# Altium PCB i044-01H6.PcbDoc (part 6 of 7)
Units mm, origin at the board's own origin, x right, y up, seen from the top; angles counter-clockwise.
Board outline 42 x 29.01 mm, 8 copper layers (Top Layer, Mid-Layer 1, Mid-Layer 2, Mid-Layer 3, Mid-Layer 4, Mid-Layer 5, Mid-Layer 6, Bottom Layer), stack 1.474 mm thick; 235 components, 197 nets, 1006 pads, 1183 vias.
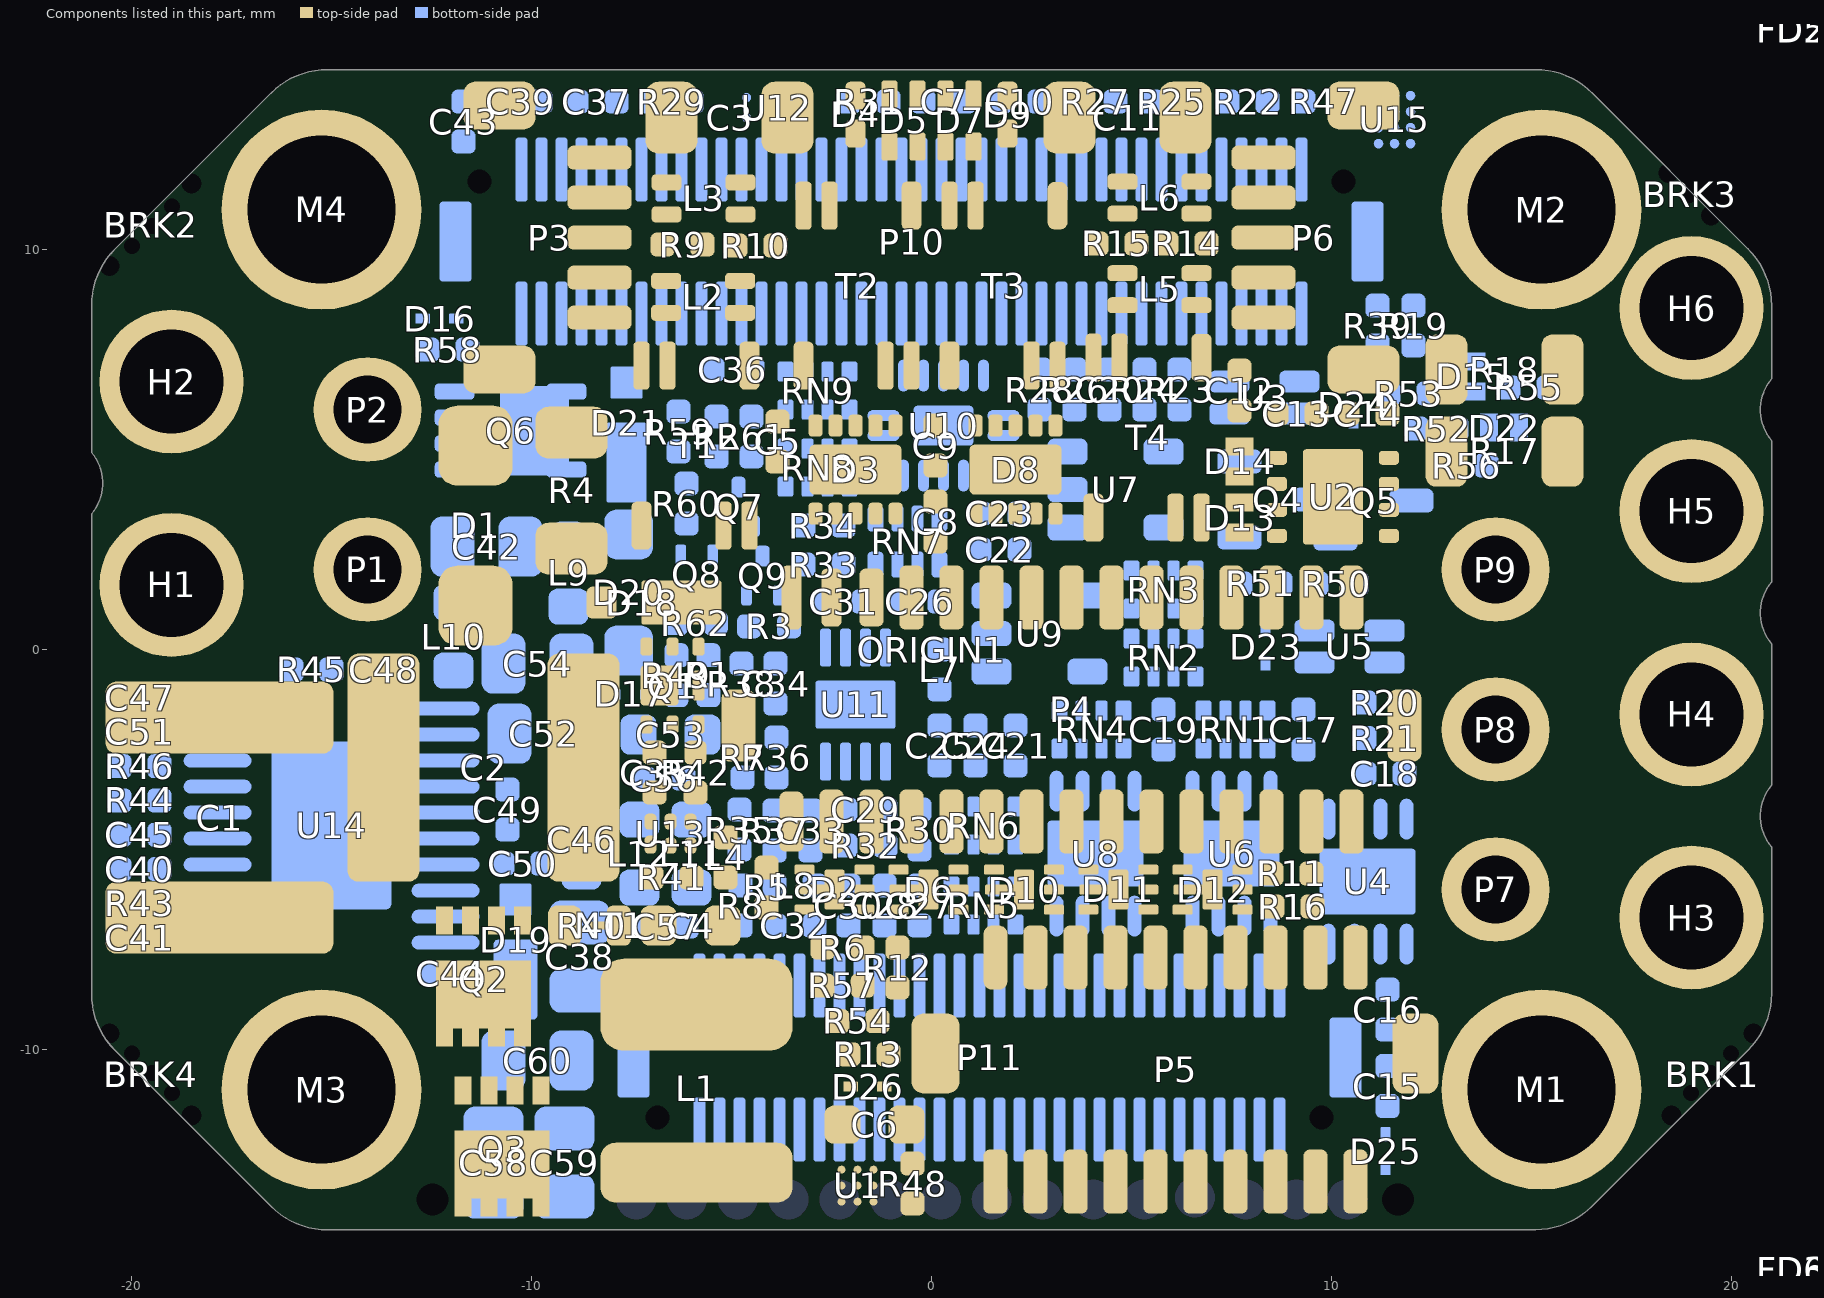
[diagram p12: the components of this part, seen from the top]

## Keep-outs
Top Layer:
  lines w0.2: 9,0.075 9,2.375 ; 10,0.035 10,2.5
  lines w0.25: 12.097,5.975 17.059,5.975
  lines w0.3: -8.075,-6.175 -4.865,-6.166 -4.601,-6.429 -4.6,-6.726 -4.048,-7.276 -3.902,-7.275 -3.227,-7.947 -3.222,-9.945 -3.777,-10.502 -3.774,-11.465 -3.535,-11.704 -3.535,-11.93 -3.259,-12.206 -3.259,-14.425 ; -3.379,-10.15 -3.373,-12.092
  lines w0.4: -9.601,0.125 -8.875,0.125 ; -8.748,0.148 -7.844,0.148 -7.55,-0.147 -7.55,-0.382
  lines w0.49: -7.875,-6.075 -7.55,-5.75 -7.55,-0.382
  lines w0.5: -19,10.3 -18.69,10.3 -16.82,8.43 -16.33,7.94 -13.12,7.94 -9.587,7.94 -9.38,7.733 ; -17.84,-12.064 cw(c-15.25,-11) -16.754,-13.362 ; -14.6,-8.3 -14.6,-6.55 -14.125,-6.075 -11.275,-6.075 ; -10.19,0.038 -10.19,0.914 -10.19,1.79 -10.19,6.01 -10.026,6.174 ; -10.025,-1.175 -10.025,-0.299 -9.951,-0.225 -9.601,0.125 ; -10.021,-0.778 -10.021,-4.821 -11.275,-6.075 ; -9.841,6.273 -9.538,6.575 -9.222,6.575 -8.722,7.075 ; -9.38,10.71 -9.38,7.733 ; -7.875,-6.075 -11.275,-6.075 ; -7.76,3.475 -7.76,3.957 -7.567,4.151 -7.567,5.92 -9.38,7.733 ; -7.76,3.7 -7.76,3.57 -7.76,2.47 -7.73,2.44 -7.53,2.24 -7.39,2.24 -6.86,2.24 -6.77,2.33 -6.32,2.78 -6.32,3.36 -6.32,4.13 -5.07,5.38 -5.07,7.8 -4.91,7.96 -4.77,7.96 -4.16,7.96 -4.05,7.85 -3.92,7.72 -3.92,7.28 -3.92,6.65 -3.71,6.44 -3.42,6.15 -3.32,6.15 -2.91,6.15 -2.8,6.26 -1.92,7.14 -1.92,9.81 -1.92,11.84 -2.31,12.23 -2.5,12.42 -2.5,14.48 ; -7.38,11.82 -7.06,12.14 -6.68,12.14 -5.94,12.14 ; -5.575,14.674 -5.575,13.202 -5.575,12.505 -5.94,12.14 ; 2.425,14.5 2.425,12.61 2.65,12.385 3.06,11.975 3.575,11.975 3.675,11.875 3.675,11.65 ; 3.246,10.247 ccw(c3.259,10.627) 3.618,10.503 ; 3.269,10.225 2.675,10.225 1.575,11.325 1.575,11.8 1.404,11.971 0.221,11.971 -0.004,11.746 -0.004,8.721 -0.05,8.675 -0.05,6.45 0.2,6.2 0.825,6.2 1.475,6.85 1.475,7.3 2.25,8.075 3.475,8.075 3.604,7.946 3.604,4.435 3.548,4.38 3.548,2.617 3.765,2.4 4.725,2.4 5.3,2.975 5.3,3.915 6.125,4.74 6.125,7.875 6.4,8.15 6.965,8.15 7.1,8.15 7.225,8.025 7.275,7.975 7.275,7.675 7.375,7.575 7.65,7.575 ; 3.665,10.565 3.665,11.715 ; 12.175,1.825 12.175,1.3 10.95,0.075 ; -5.94,12.14 -5.94,12.14 ; 8.175,2.375 7.15,2.375 7.05,2.275 7.05,0.25 7.225,0.075 8.225,0.075 ; 8.175,2.375 8,2.2 8,0.3 8.225,0.075 ; 8.175,2.375 9.873,2.375 10.793,2.375 11.079,2.089 11.079,0.204 10.95,0.075 ; 8.225,0.075 10.95,0.075
  lines w0.6: 7.55,7.6 9.125,7.6 9.65,7.6 10,7.95 11.85,7.95 12.1,8.2 13.75,8.2 15.325,8.2 16.435,8.2 17.05,7.585 17.05,4.538 16.396,3.884 16.075,3.725 12.375,3.725 ; 11.95,8.05 12.025,7.975 12.025,6.771 12.025,4.1 12.35,3.775 12.35,2.3 12.35,2 12.175,1.825
Mid-Layer 1:
  circle w0.5: c15.25,-11 r2.26
  circle w0.5: c-15.25,-11 r2.26
  circle w0.4: c-15.25,11 r2.3
  lines w0.2: 0.825,11.6 2.65,11.6 2.875,11.825 2.875,13.225 2.643,13.408 2.591,13.85 2.636,13.895 5.415,13.895 5.605,13.705 5.605,12.68 5.605,12.37
  lines w0.3: -7.525,-4.95 -7.523,-5.744 -7.093,-6.172 -4.865,-6.166 -4.601,-6.429 ; -4.048,-7.276 -4.6,-6.726 ; -4.002,-7.268 -3.993,-10.467 -3.709,-10.75 ; -3.223,-9.425 -3.223,-9.399 ; -4.601,-6.429 -4.6,-6.726 ; -4.601,-6.429 -4.6,-6.726
  lines w0.4: -11.35,-7.6 -9.887,-7.6 -9.887,-9.161 -7.788,-11.26 -7.26,-11.26 -7.062,-11.062 ; -11.35,-7.598 -13.243,-7.598 -13.725,-8.08 -13.725,-9.181 -12.975,-9.931 -12.975,-12.6 -13.25,-12.875 -13.25,-14.234 -12.984,-14.5 -7.775,-14.5 -7.775,-13.6 -5.993,-11.818 -5.993,-11.875 ; -7.8,-14.5 -3.575,-14.5 -3.425,-14.35 -3.425,-11.675 -3.625,-11.875 -5.993,-11.875 ; -7.062,-11.062 -6.43,-11.062 ; -7.062,-11.062 -6.43,-11.062 ; -6.43,-11.062 -6.267,-11.225 -6.267,-11.601 -5.993,-11.875
  lines w0.5: -14.2,14.499 -12.403,12.702 -12.403,9.103 -10.991,7.691 ; -11.25,7.975 -10.346,7.03 -10.068,6.753 -10.068,2.408 -8.96,1.3 -7.575,-0.085 -7.575,-5.023 ; -3.709,-10.75 -3.49,-10.969 -3.49,-11.175 -3.49,-11.675 ; -3.15,-14.275 -3.15,-13.591 ; 1.571,11.746 -0.004,11.746 -0.004,8.721 -0.004,6.404 0.2,6.2 1.475,6.2 1.475,6.595 1.921,7.041 1.921,7.621 2.246,7.946 ; 2.82,13.725 5.4,13.725 5.4,12.449 5.709,12.14 6.908,12.14 7.658,12.89 9.16,12.89 9.575,12.475 9.575,9.025 8.15,7.6 6.75,7.6 6.125,6.975 6.125,4.4 5.64,3.915 5.129,3.404 3.885,3.404 3.604,3.685 3.604,8.04 ; 15.25,8.74 cw(c15.25,11) 16.962,12.475 ; -9.38,7.68 -7.575,5.875 -7.575,3.755 -7.575,3.385 -7.575,2.655 -7.345,2.425 -6.675,2.425 -6.32,2.78 -6.32,3.36 -6.32,4.765 -5.705,5.38 -5.07,5.38 -4.01,6.44 -3.71,6.44 -3.4,6.75 -2.31,6.75 -1.92,7.14 -1.92,9.81 -1.92,11.84 -2.31,12.23 -2.31,12.711 -2.31,13.447 -2.61,13.747 -2.61,14.48 -2.615,14.475 -5.575,14.475 -5.575,13.202 -5.575,12.505 -5.94,12.14 -6.68,12.14 -7.06,12.14 -8.56,12.14 -9.38,11.32 -9.38,7.68
Mid-Layer 2:
  circle w0.5: c15.25,-11 r2.26
  circle w0.5: c-15.25,-11 r2.26
  circle w0.4: c-15.25,11 r2.3
  lines w0.2: 2.6,12.325 2.9,12.625 2.9,12.975 2.65,13.95
  lines w0.3: -4.6,-6.726 -4.048,-7.276 -3.227,-8.093 -3.223,-9.425
  lines w0.4: -13.167,-14.475 -13.167,-11.898 ; -7.8,-14.5 -3.575,-14.5 -3.425,-14.35 ; -7.462,-12.688 -7.775,-13 -7.775,-14.5 ; -13.167,-14.5 -13.167,-11.898 ; -13.167,-14.5 -7.775,-14.5 ; -13.167,-14.5 -7.775,-14.5 ; -13.167,-11.898 -12.918,-11.65 -13.167,-11.898
  lines w0.48: -8.403,1.265 -8.051,0.913 ; -7.575,-4.536 -6.884,-5.227 -6.318,-5.227 -5.663,-5.882 -5.438,-5.882 -4.603,-6.716 ; -7.462,-12.688 -7.462,-11.488 -6.8,-10.825
  lines w0.5: -20.7,4.2 -12.475,4.2 ; -14.2,14.499 -12.475,12.774 -12.475,5.95 -12.475,0.863 ; -12.92,0.418 -11.531,0.463 ; -12.875,0.463 -11.531,0.463 ; -12.418,8.207 -10.175,5.965 -10.175,2.129 -9.671,1.625 ; -12.413,0.925 -13.213,0.125 ; -9.15,1.5 -8.638,1.5 ; -7.575,-4.536 -7.575,-0.04 -7.575,0.437 -8.403,1.265 -8.638,1.5 ; -6.8,-10.825 -4.603,-8.628 -4.603,-6.716 ; -3.15,-14.275 -3.15,-9.114 ; 15.25,8.74 cw(c15.25,11) 16.962,12.475 ; -17.8,-0.6 -21,-0.6 -17.8,-0.6 ; -17.8,-0.6 -16.047,0.1 ; -17.8,-0.6 -16.047,0.1 ; -16.047,0.1 -13.213,0.125 ; -16.047,0.1 -13.213,0.125 ; -16.047,0.1 -13.213,0.125 ; -13.213,0.125 -12.475,0.863 ; -13.213,0.125 -12.475,0.863 ; -11.531,0.463 -10.994,1 -10.494,1.5 -8.637,1.5 ; -9.38,7.68 -7.575,5.875 -7.575,3.755 -7.575,3.385 -7.575,2.655 -7.345,2.425 -6.675,2.425 -6.32,2.78 -6.32,3.36 -6.32,4.755 -5.695,5.38 -5.07,5.38 -4.01,6.44 -3.71,6.44 -2.62,6.44 -1.92,7.14 -1.92,9.81 -1.92,11.84 -2.31,12.23 -2.61,12.53 -2.61,14.48 -2.615,14.475 -5.575,14.475 -5.575,13.202 -5.575,12.505 -5.94,12.14 -6.68,12.14 -7.06,12.14 -7.325,11.875 -8.825,11.875 -9.38,11.32 -9.38,7.68 ; -0.004,6.404 0.2,6.2 0.825,6.2 1.475,6.85 1.475,7.175 2.246,7.946 3.429,7.946 3.604,7.771 3.604,3.685 4,3.288 5.013,3.288 5.64,3.915 6.125,4.4 6.125,6.975 6.75,7.6 8.15,7.6 9.575,9.025 9.575,14.325 2.6,14.325 2.6,12.325 2.6,12.061 2.314,11.775 1.6,11.775 1.404,11.971 0.221,11.971 -0.004,11.746 -0.004,8.721 -0.004,6.404
Mid-Layer 3:
  circle w0.5: c15.25,-11 r2.26
  circle w0.5: c-15.25,-11 r2.26
  circle w0.4: c-15.25,11 r2.3
  rectangle: -7.85,-4.525 -5.25,-3.8
  lines w0.4: -13.167,-14.5 -3.335,-14.5 ; -13.167,-14.475 -13.167,-11.898
  lines w0.48: -8.5,0.922 -8.051,0.473 -8.051,-4.015 -6.839,-5.227 -5.473,-5.227 -4.7,-6 -4.7,-8.26 ; -7.526,-4.54 -6.19,-5.875 -4.85,-5.875 ; -7.278,-4.602 -5.475,-4.602 ; -6.975,-4.977 -5.45,-4.977 ; -6.221,-5.575 -5.614,-5.575 -4.766,-6.423 ; -5.5,-5.875 -5.5,-4.072
  lines w0.5: -20.7,4.2 -12.475,4.2 ; -14.2,14.499 -12.475,12.774 -12.475,5.95 -12.475,0.863 ; -12.875,0.463 -11.531,0.463 -10.994,1 -10.494,1.5 -9.078,1.5 ; -12.426,0.912 -13.213,0.125 ; -10.175,5.15 -10.175,5.965 ; -8.5,0.922 -9.078,1.5 ; -4.65,-8.26 -3.15,-9.76 -3.15,-14.275 ; 15.25,8.74 cw(c15.25,11) 16.962,12.475 ; -17.8,-0.6 -21,-0.6 -17.8,-0.6 ; -17.8,-0.6 -16.047,0.1 ; -17.8,-0.6 -16.047,0.1 ; -16.047,0.1 -13.213,0.125 ; -16.047,0.1 -13.213,0.125 ; -16.047,0.1 -13.213,0.125 ; -13.213,0.125 -12.475,0.863 ; -13.213,0.125 -12.475,0.863 ; -10.175,5.965 -12.418,8.207 -10.175,5.965 ; -10.175,5.965 -10.175,2.129 -9.546,1.5 -9.078,1.5
Mid-Layer 4:
  circle w0.5: c15.25,-11 r2.26
  circle w0.5: c-15.25,-11 r2.26
  circle w0.4: c-15.25,11 r2.3
  lines w0.4: -13.167,-14.5 -7.775,-14.5 ; -13.167,-14.475 -13.167,-11.995 ; -7.775,-14.5 -7.775,-12.525 -7.775,-14.5
  lines w0.48: -9.484,0.718 -8.579,0.718 ; -7.9,-4.977 -5.723,-4.977 -5.2,-5.5 ; -7.775,-12.525 -7.05,-12.525 -6.275,-11.75 -6.275,-11.05 -4.85,-9.625 -4.85,-5.85 -5.473,-5.227 -7.65,-5.227 -8.051,-4.826 -8.051,0.19 ; -8.579,0.718 -8.051,0.19 ; -8.579,0.718 -8.051,0.19
  lines w0.5: -20.7,4.2 -12.475,4.2 ; -14.2,14.499 -12.475,12.774 -12.475,5.95 -12.475,0.863 ; -12.875,0.463 -11.531,0.463 ; -12.425,2.775 -11.443,1.793 ; -12.375,1.793 -10.201,1.793 -8.87,1.793 -8.579,1.502 -8.579,0.718 ; -8.125,0.225 -8.7,0.8 -10.968,0.8 -11.349,0.418 -12.92,0.418 -13.213,0.125 ; 15.25,8.74 cw(c15.25,11) 16.962,12.475 ; -17.8,-0.6 -21,-0.6 -17.8,-0.6 ; -17.8,-0.6 -16.047,0.1 ; -17.8,-0.6 -16.047,0.1 ; -16.047,0.1 -13.213,0.125 ; -16.047,0.1 -13.213,0.125 ; -16.047,0.1 -13.213,0.125 ; -13.213,0.125 -12.475,0.863 ; -13.213,0.125 -12.475,0.863
Mid-Layer 5:
  circle w0.4: c-15.25,11 r2.3
  circle w0.5: c15.25,-11 r2.26
  circle w0.5: c-15.25,-11 r2.26
  rectangle: -8.1,-5.15 -5.25,-3.8
  lines w0.3: -5.3,-5.4 -5.3,-4.977
  lines w0.4: -13.167,-12.008 -13.167,-14.5 -7.775,-14.5 ; -7.775,-13 -7.775,-14.5 ; -7.575,-12.4 -7.775,-12.6 -7.775,-14.5
  lines w0.48: -9.484,1.793 -8.579,1.793 -8.051,1.265 -8.051,-4.826 -7.65,-5.227 -5.473,-5.227 -4.875,-5.825 -4.875,-9.635 -6.275,-11.035 -6.275,-12.4 -7.575,-12.4 ; -7.9,-4.977 -5.4,-4.977 ; -6.282,-10.882 -6.273,-8.979 -5.672,-8.383 -5.099,-8.386
  lines w0.5: -20.7,4.2 -12.475,4.2 ; -14.2,14.499 -12.475,12.774 -12.475,5.95 -12.475,0.863 ; -12.875,0.463 -11.531,0.463 ; -12.425,2.775 -11.443,1.793 -11.288,1.793 ; -12.375,1.793 -10.201,1.793 -8.775,1.793 ; -8.051,0.8 -10.968,0.8 -11.349,0.418 -12.92,0.418 -13.213,0.125 ; 15.25,8.74 cw(c15.25,11) 16.962,12.475 ; -17.8,-0.6 -21,-0.6 -17.8,-0.6 ; -17.8,-0.6 -16.047,0.1 ; -17.8,-0.6 -16.047,0.1 ; -16.047,0.1 -13.213,0.125 ; -16.047,0.1 -13.213,0.125 ; -16.047,0.1 -13.213,0.125 ; -13.213,0.125 -12.475,0.863 ; -13.213,0.125 -12.475,0.863
Mid-Layer 6:
  circle w0.4: c-15.25,11 r2.3
  circle w0.5: c15.25,-11 r2.26
  circle w0.5: c-15.25,-11 r2.26
  circle w0.3: c10.975,3.2 r0.469
  circle w0.3: c10,3.225 r0.469
  circle w0.3: c8.25,3.775 r0.469
  rectangle: -8.1,-5.15 -5.25,-3.8
  lines w0.3: -10.575,7.25 -10.45,7.125 -8.282,7.125 ; -5.3,-5.4 -5.3,-4.75 -5.3,-3.95 ; 10.111,4.5 10.638,4.5 10.925,4.787 10.925,5.2 ; 10.92,5.211 10.92,5.445 11.55,6.075 11.55,6.35
  lines w0.4: -13.167,-12.031 -13.167,-14.5 -7.775,-14.5 -7.775,-13 -7.65,-12.875 ; -8.975,-14.525 -8.854,-14.525 ; -5.934,-8.398 -5.55,-8.013
  lines w0.48: -8.825,1.986 -8.051,1.212 -8.051,0.8 -8.051,-4.826 -7.65,-5.227 -5.473,-5.227 -5.1,-5.6 -5.1,-7.425 -5.55,-7.875 -5.55,-8.013 ; -7.9,-4.977 -5.4,-4.977 ; -7.65,-12.875 -6.75,-12.875 -6.275,-12.4 ; -6.285,-11.475 -6.271,-8.596 -6.073,-8.398 -5.934,-8.398 ; -6.275,-9.425 -5.65,-10.05 -5.65,-10.475 -6.271,-11.096 -6.271,-12.4
  lines w0.5: -21,-0.6 -17.8,-0.6 -16.047,0.1 ; -20.7,4.2 -12.475,4.2 ; -14.2,14.499 -12.069,12.368 -12.069,8.675 -12.842,8.675 ; -12.875,0.463 -11.531,0.463 ; -12.525,8.675 -12,8.675 -10.575,7.25 ; -12.475,6.79 -12.475,0.863 -13.213,0.125 ; -8.825,1.986 -8.825,3.947 -8.81,3.962 -8.81,4.789 -8.81,5.765 ; -8.825,2.453 -10.478,0.8 -10.968,0.8 ; -8.051,0.8 -10.968,0.8 ; 6.95,2.4 6.875,2.475 6.875,3.925 6.875,4.86 7.24,5.225 9.386,5.225 10.111,4.5 ; 7.075,2.275 7.075,1.595 7.91,0.76 7.91,-0.129 8.307,-0.525 10.3,-0.525 10.3,-0.173 10.425,-0.048 10.425,0.685 10.79,1.05 11.968,1.05 12.4,1.482 12.4,3.371 13.179,4.15 16.3,4.15 16.625,4.475 16.625,7.04 15.94,7.725 14.075,7.725 13.53,7.18 12.38,7.18 12.075,6.875 11.55,6.35 ; 15.25,8.74 cw(c15.25,11) 16.962,12.475 ; -16.047,0.1 -13.213,0.125 ; -16.047,0.1 -13.213,0.125 ; -13.213,0.125 -12.92,0.418 -11.349,0.418 ; -11.349,0.418 -10.968,0.8 ; -11.349,0.418 -10.968,0.8
Bottom Layer:
  lines w0.19: -5.98,-1.45 -5.98,-0.87
  lines w0.198: -5.11,3.93 -5.11,4.38 ; -4.85,3.69 cw(c-4.84,3.69) -4.84,3.7 -4.625,3.7 -4.025,4.3 ; -2.5,7.481 -2.046,7.481 -2,7.527 -2,9.2 -2.1,9.3 -2.4,9.3 -2.5,9.2 -2.5,7.481 ; -2.5,11.2 -2.5,12.8 -2.376,12.924 -2,12.924 -2,11.2 -2.1,11.1 -2.4,11.1 -2.5,11.2
  lines w0.2: -11.086,1.525 -9.925,1.525 -9.715,1.735 -8.603,1.735 -8.35,1.482 -8.35,-1.25 -8.051,-1.549 ; -8.051,-1.625 -8.051,-1.549 ; -7.61,-1.46 -6.965,-1.46 -6.875,-1.55 -6.08,-1.55 -5.98,-1.45 ; -6.875,5.425 -5.943,5.425 -5.843,5.325 -5.2,5.325 -4.925,5.6 -4.925,6.275 ; -6.8,-0.57 -6.28,-0.57 -5.98,-0.87 ; -5.9,6.4 -6.725,6.4 -6.9,6.225 -6.9,5.43 -6.74,5.27 -6.74,3.961 -6.53,3.751 -6.53,1.52 -6.8,1.25 -6.8,-0.562 -7.011,-0.774 -7.334,-0.774 -7.49,-0.93 -7.49,-1.325 -7.714,-1.549 -8.051,-1.549 ; -5.868,6.4 -5.868,4.618 -5.625,4.375 -5.1,4.375 ; -5.3,-4.75 -5.3,-3.95 -5.55,-3.7 -5.55,-2.975 -5.145,-2.57 -5.145,-1.712 -5.175,-1.682 -5.175,-0.075 -5.029,0.071 -3.32,0.071 -3.125,0.266 -3.125,1.35 -3.625,1.85 -3.625,3.3 -3.975,3.65 ; -5.125,4.35 cw(c-5.1,4.35) -5.1,4.375 ; -5.115,3.945 ccw(c-4.86,3.945) -4.86,3.69 ; -4.05,5.3 -4.7,5.3 -4.95,5.05 -4.95,4.525 -5.1,4.375 ; -3.975,3.725 -3.975,3.65 ; -3.975,4.45 -3.975,3.65 ; 7.075,5.3 6.8,5.575 4.219,5.575 4.025,5.769 4.025,6.297 4.185,6.457 6.593,6.457 6.76,6.29 8,6.29 ; 8.211,5.3 8.375,5.136 8.375,3.525 9.175,2.725 9.175,2.65 9.475,2.35 10.65,2.35 11.275,1.725 ; 10.2,0.651 10.2,0.968 9.932,1.235 8.25,1.235 8.025,1.01 8.025,0.25 8.2,0.075 10.45,0.075 10.425,0.1 ; 10.425,-0.675 10.85,-0.675 11.2,-1.025 11.425,-1.025 ; 10.461,0.086 10.925,0.086 11.789,0.086 11.839,0.086 11.95,-0.025 11.95,-0.625 11.7,-0.875 11.575,-0.875 11.425,-1.025 ; 11.275,4.24 9.165,4.24 8.925,4 8.925,3.502 9.102,3.325 11.05,3.325 11.325,3.6 11.325,4.19 ; 12.275,-3.538 11.45,-3.538 11.35,-3.438 11.35,-1.1 11.425,-1.025 ; 12.893,7.15 12.893,6.282 13.166,6.009 13.634,6.009 13.725,6.1 16.306,6.1 16.825,6.619 16.825,7.05
  lines w0.3: -5.3,-7.323 -5.3,-5.425 ; -5.3,-5.4 -5.3,-4.75
  lines w0.32: -4.025,4.3 -4.025,5.975 -4.025,6.475
  lines w0.4: -10.477,7.3 -9.075,7.325 -6.25,7.325
  lines w0.48: -8.175,-14.475 -8.175,-13.4 -7.65,-12.875 -6.75,-12.875 -6.275,-12.4 -6.275,-7.505 -6.095,-7.325 -5.475,-7.325 ; -8.051,-1.625 -8.051,-4.826 -7.65,-5.227 -5.473,-5.227 ; -7.9,-4.977 -5.4,-4.977
  lines w0.5: -20.937,-0.563 -17.85,-0.563 ; -20.925,8.8 -17.575,8.8 -17.05,8.275 -16.575,7.8 -14.458,7.8 ; -17.875,-0.549 -16.072,0.114 ; -16.047,0.1 -13.213,0.125 -12.92,0.418 -11.482,0.418 -11.086,0.814 -11.086,1.525 ; -12.864,8.944 -11.676,8.944 -11.343,8.61 -10.675,7.942 -10.675,7.498 -10.477,7.3 ; -6.5,7.25 -6.2,7.25 -6.05,7.1 -6.05,6.582 -5.868,6.4 -5.9,6.4 -4.2,6.4 ; 11.275,1.1 11.275,1.725 13.5,3.95 13.875,3.95 13.9,3.925 14.575,3.925 16.025,3.925 17.425,5.325 17.637,5.537 18.739,5.737 20.821,5.737 ; 12.1,-14.499 12.1,-9.1 12.446,-8.754 ; 12.446,-1.204 12.625,-1.025 12.625,0.488 12.063,1.05 10.575,1.05 10.425,0.9 10.425,-0.675 10.225,-0.875 8.975,-0.875 7.775,-0.875 ; 13.325,7.75 16.042,7.75 ; 13.575,7.75 13.1,7.75 12.35,7 10.85,7 9.975,7 9.675,7.3 8.75,7.3 8.4,6.95 8.211,6.761 8.211,5.3 7.075,5.3 6.875,5.1 6.875,3.925 6.875,2.475 6.95,2.4 6.97,2.38 7,2.35 7.075,2.275 7.075,1.075 7.475,0.675 7.475,-0.575 7.775,-0.875 ; 14.895,7.75 16.042,7.75 ; 18.4,5.7 18.4,6.297 17.9,6.797 17.003,6.797 16.1,7.7 16.092,7.7 16.042,7.75 ; 7.775,-0.875 7.775,-0.875
  lines w0.6: -17.04,8.408 ccw(c-15.25,11) -12.864,8.944 ; -15.118,14.197 cw(c-15.25,11) -12.124,11.683 -11.046,11.683 -11.046,8.65 ; 12.446,-8.754 12.446,-1.204 ; 14.33,-14.065 cw(c15.25,-11) 18.202,-9.766 ; 15.118,7.803 cw(c15.25,11) 17.827,12.897
  lines w0.8: -18.449,-10.926 cw(c-15.25,-11) -15.631,-14.177
Keep-Out Layer:
  circle w0.15: c-12.475,-13.745 r0.45
  circle w0.2: c11.665,-13.745 r0.51
  lines w0.25: 11.7,-13.2 12.825,-13.2
  lines w0.5: -21,-0.475 -21,-8.8 -20.923,-9.186 -20.772,-9.55 -20.554,-9.878 -20.414,-10.017 -16.514,-13.916 -16.375,-14.055 -16.047,-14.274 -15.683,-14.425 -15.297,-14.502 -15.1,-14.502 15.1,-14.498 15.297,-14.498 15.683,-14.422 16.047,-14.271 16.375,-14.052 16.514,-13.913 20.414,-10.014 20.554,-9.875 20.772,-9.547 20.923,-9.183 21,-8.797 ; -21,8.797 -20.923,9.183 -20.772,9.547 -20.554,9.875 -20.414,10.014 -16.514,13.913 -16.375,14.052 -16.047,14.271 -15.683,14.422 -15.297,14.498 -15.1,14.498 15.1,14.502 15.297,14.502 15.683,14.425 16.047,14.274 16.375,14.055 16.514,13.916 18.003,12.428 ; -20.782,3.697 -20.7,4.002 -20.7,4.318 -20.782,4.623 ; 12.45,-4 12.6,-4.15 16.037,-4.15 20.7,-4.15 ; 12.5,0 15.8,0 16.7,0.9 20.7,0.9 ; 13.8,-8.275 13.25,-8.275 12.875,-7.9 12.475,-7.5 12.475,-0.8 12.475,0 12.475,3.5 13.1,4.125 14.6,4.125 16.3,4.125 16.475,4.3 16.725,4.55 16.725,4.8 18,6.075 18.35,6.075 ; 16.625,7.85 17.7,6.775 17.7,6.625 18.325,6 20.675,6 ; 20.7,5.842 20.782,5.537 ; 20.782,-3.697 20.7,-4.002 20.7,-4.318 20.786,-4.638 ; 20.782,0.457 20.7,0.762 20.7,1.078 20.782,1.383

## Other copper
Top Layer:
  rectangle net +5V_OUT: 6.9,-2.875 8.025,-0.95
  rectangle net GND_D: -1.05,13.525 1.125,14.225
  rectangle net MAGNETICS_CT: 0.1,5.325 1.175,5.875
  rectangle net GND_D: -4.2,3.875 3.2,5.1
  region net 5V_D: -2.75,-12.425 -2.656,-12.519 cw(c-2.912,-12.775) -2.55,-12.775 -2.55,-13.975 cw(c-2.7,-13.975) -2.7,-14.125 -2.975,-14.125 cw(c-2.975,-14) -3.1,-14 -3.1,-12.075
  region net +5V_OUT: -1.36,-10.725 -1.4,-10.765 -1.4,-11.061 cw(c-1.639,-11.061) -1.47,-11.23 -1.513,-11.273 ccw(c-1.379,-11.416) -1.575,-11.41 -1.575,-11.855 ccw(c-0.38,-11.855) -1.225,-12.7 -1.05,-12.7 cw(c-0.7,-12.7) -0.7,-12.35 -0.65,-12.35 0.097,-12.35 cw(c0.097,-12.672) 0.325,-12.444 cw(c0.144,-12.625) 0.4,-12.626 0.4,-13.8 ccw(c0.675,-13.8) 0.675,-14.075 1.725,-14.075 ccw(c1.725,-13.9) 1.9,-13.9 1.9,-12.626 ccw(c1.677,-12.626) 1.835,-12.468 ccw(c1.015,-13.288) 1.015,-12.129 0.897,-12.129 cw(c0.897,-11.144) 0.2,-11.84 -0.175,-11.465 ccw(c-0.356,-11.646) -0.331,-11.391 -0.409,-11.391 cw(c-0.409,-11) -0.8,-11 -0.8,-10.923 ccw(c-0.998,-10.923) -0.998,-10.725 -1.35,-10.725 ccw(c-1.35,-10.954)
  region net GND_D: -1.85,-10.725 cw(c-1.85,-10.775) -1.8,-10.775 -1.8,-11.182 ccw(c-1.732,-11.182) -1.78,-11.23 -1.771,-11.239 cw(c-1.822,-11.29) -1.75,-11.29 -1.75,-12.7 -1.85,-12.8 -1.925,-12.8 -2.663,-12.062 -2.65,-10.85 cw(c-2.525,-10.85) -2.525,-10.725
  region net GND_D: -3.575,2.075 ccw(c-3.575,1.653) -3.874,1.951 -4.025,1.8 cw(c-4.447,2.222) -4.447,1.625 -4.475,1.625 ccw(c-4.475,1.5) -4.6,1.5 -4.6,1.325 ccw(c-4.45,1.325) -4.45,1.175 -4.25,1.175 cw(c-4.25,0.934) -4.079,1.104 -3.788,0.813 ccw(c-3.575,1.027) -3.575,0.725
  region net BRAKE_OUT: -7.114,0.296 -7.203,0.296 -7.875,0.968 -7.875,1.372 -8.075,1.572 -9.488,1.572 ccw(c-9.488,1.35) -9.71,1.35 -9.71,0.76 ccw(c-9.475,0.76) -9.475,0.525 -8.269,0.525 cw(c-8.269,-0.539) -7.516,0.213 -7.414,0.111 cw(c-7.75,-0.225) -7.275,-0.225 -7.275,-1.95 ccw(c-7.125,-1.95) -7.125,-2.1 -6.475,-2.1 ccw(c-6.475,-1.95) -6.325,-1.95 -6.325,0.25 ccw(c-6.375,0.25) -6.375,0.3 -7.075,0.3 ccw(c-7.075,0.1)
  region net GND_D: -5.517,-1.617 cw(c-5.521,-1.689) -5.45,-1.693 -5.45,-2.4 ccw(c-5.325,-2.4) -5.325,-2.525 cw(c-5.325,-2.6) -5.25,-2.6 -5.25,-2.75 -5.25,-3.95 ccw(c-5.1,-3.95) -5.1,-4.1 -4.2,-4.1 ccw(c-4.2,-3.9) -4,-3.9 -4,-3.5 cw(c-3.8,-3.5) -3.8,-3.3 -3.246,-3.3 ccw(c-3.246,-3.131) -3.2,-3.294 -3.2,-1.642 ccw(c-3.265,-1.817) -3.265,-1.63 -4.147,-1.63 cw(c-4.147,-1.32) -4.457,-1.32 ccw(c-4.777,-1.32) -4.777,-1 -5.262,-1 -5.787,-0.475 -5.876,-0.475 -5.975,-0.574 -5.975,-1.284 -5.9,-1.359 -5.776,-1.359
  region net +LOGIC_DCDC: -11.925,-12.025 -9.561,-12.025 cw(c-9.561,-12.163) -9.423,-12.163 -9.423,-14.168 -11.925,-14.168
  region net GND_DCDC: -6.485,-6.34 -6.4,-6.425 -6.4,-7.303 cw(c-6.556,-7.303) -6.556,-7.459 -7.94,-7.459 cw(c-7.94,-7.259) -8.14,-7.259 -8.14,-6.34
  region net NetC44_1: -8,-11.925 -7.529,-11.925 cw(c-7.529,-12.176) -7.352,-11.998 -7.156,-12.194 ccw(c-6.96,-11.997) -6.96,-12.275 -6.771,-12.275 ccw(c-6.771,-11.923) -6.522,-12.172 -6.351,-12.001 cw(c-6.207,-12.145) -6.207,-11.941 -4.009,-11.941 cw(c-4.009,-12.5) -3.45,-12.5 -3.45,-13.65 cw(c-4.025,-13.65) -4.025,-14.225 -7.975,-14.225 cw(c-7.975,-13.65) -8.55,-13.65 -8.55,-12.475 cw(c-8,-12.475)
  region net GND_P: -10.546,-0.657 -10.546,2.16 ccw(c-11.106,2.16) -11.106,2.72 -12.261,2.72 cw(c-12.261,3.539) -12.84,2.96 ccw(c-13.894,1.907) -13.068,3.147 ccw(c-14.161,2.053) -14.162,3.6 -18.259,3.6 ccw(c-18.259,3.259) -18.5,3.5 cw(c-18.781,3.77) -18.6,3.425 -20.9,3.425 -21,3.325 -20.998,3.3 -20.998,-0.102 -20.7,-0.4 -20.7,-4.965 ccw(c-20.465,-4.965) -20.465,-5.2 -15.452,-5.2 -15.183,-5.2 cw(c-15.183,-5.882) -14.7,-5.4 ccw(c-13.371,-4.071) -14.108,-5.8 -11.845,-5.8 ccw(c-11.845,-5.156) -11.361,-5.58 -11.085,-5.265 -10.826,-5.006 ccw(c-11.493,-4.339) -10.55,-4.339 -10.55,-1.524 cw(c-8.635,-1.524) -10.548,-1.43 -10.548,-0.728 cw(c-9.102,-0.728)
  region net PE: 20.5,6.739 20.5,8.702 ccw(c18.877,8.533) 20.031,9.687 19.734,9.984 20.091,10.341 20.484,9.948 cw(c19.238,8.702) 21,8.702 21,6.739
  region net ETH0_TX_P: -9.1,8.3 -9.1,8.05 ccw(c-8.575,8.05) -8.575,7.525 -8.275,7.525 ccw(c-8.275,8.3) -7.5,8.3
  region net PE3: 12.138,-8.225 ccw(c13.215,-7.149) 13.215,-8.671 14.8,-8.671 ccw(c14.8,-10.185) 13.73,-9.114 13.563,-9.281 13.376,-9.463 ccw(c14.541,-10.628) 12.893,-10.629 12.893,-11.45 ccw(c13.52,-11.558) 13,-11.925 13.167,-12.225 13.648,-12.8 14.57,-13.366 14.678,-13.475 14.562,-13.475 cw(c14.562,-9.884) 12.023,-12.423 cw(c13.226,-11.22) 11.525,-11.22 ccw(c9.376,-11.22) 10.993,-9.805 cw(c12.569,-8.426) 10.475,-8.426 10.475,-7.091 10.725,-6.841 10.725,-5.163 10.5,-4.938 10.5,-3.6 10.6,-3.5 10.727,-3.5 cw(c10.727,-4.28) 11.279,-3.729 11.442,-3.892 cw(c11.06,-4.274) 11.6,-4.274 11.6,-6.926 ccw(c13.438,-6.926)
  region net PH_C: 15.411,0.7 ccw(c15.411,1.639) 16.075,0.975 cw(c17.765,-0.715) 17.765,1.675 18.325,1.675 20.55,1.675 20.55,5.3 19.261,5.3 ccw(c19.261,2.951) 17.6,4.612 16.839,3.851 cw(c15.481,5.208) 15.481,3.288 14.005,3.288 ccw(c14.005,2.034) 12.75,2.034 12.75,1.85 ccw(c13.9,1.85) 13.9,0.7
  region net PH_B: 18.875,0.186 18.117,0.186 ccw(c18.117,-1.909) 16.636,-0.428 cw(c16.038,0.17) 16.038,-0.675 14.05,-0.675 ccw(c14.05,-1.975) 12.75,-1.975 ccw(c14.205,-1.975) 14.205,-3.43 20.509,-3.43 ccw(c20.042,-3.4) 20.51,-3.4 ccw(c20.51,-3.285) 20.625,-3.285 20.625,0.025 ccw(c20.051,0.025) 20.602,0.186
  region net PH_A: 14.919,-4.884 13.57,-4.884 ccw(c13.57,-5.496) 13.137,-5.063 ccw(c14.074,-5.999) 12.75,-6 ccw(c14.025,-6) 14.025,-7.275 16.495,-7.275 cw(c16.495,-8.555) 17.4,-7.65 17.509,-7.759 ccw(c19.341,-5.927) 19.341,-8.517 20.596,-8.517 ccw(c19.868,-8.535) 20.578,-8.375 20.55,-5.925 20.55,-4.9 15.018,-4.9 cw(c15.018,-4.582)
  region net +V_BUS: -10.253,6.408 ccw(c-9.766,5.911) -10.462,5.918 -10.465,4.496 cw(c-11.125,4.848) -11.125,4.1 -12.117,4.1 cw(c-12.117,4.783) -12.18,4.103 -12.316,4.103 cw(c-12.316,5.459) -13.275,4.5 ccw(c-13.697,4.078) -13.697,4.675 -17.145,4.675 cw(c-17.145,4.965) -17.201,4.681 -18.209,4.681 cw(c-18.209,5.088) -18.498,4.8 ccw(c-18.79,4.508) -18.92,4.9 -20.9,4.9 -21,5 -20.996,8.404 -20.813,8.587 -20.565,8.587 -19.1,8.587 cw(c-19.095,6.15) -18.902,8.58 -18.415,8.58 cw(c-18.414,7.005) -17.3,8.118 ccw(c-15.747,9.671) -16.783,7.734 -16.584,7.652 -16.32,7.6 -14.146,7.6 -10.43,7.6 cw(c-10.43,6.305) -10.054,7.544 -10.054,6.446
  region net GND_D: 10.575,5.55 10.575,5.075 10.775,4.875 10.775,3.775 9.275,3.775 9.275,6.677 10.148,7.55 10.75,7.55 11.1,7.2 11.1,6.425
  region net NetQ2_1: -9.025,-6.4 -11.754,-6.4 -11.754,-7.4 -9.02,-7.4 -9.02,-7.326
  region net GND_D: 8.975,-2.925 8.975,-1.675 8.225,-1.675 8.2,-1.7 8.2,-2.4 8.2,-3.354 8.2,-4.304 8.8,-4.296 8.8,-3.1
  region net GND_D: 8.9,-13.296 8.9,-12.329 8.975,-12.254 8.975,-11.456 8.9,-11.381 8.2,-11.381 8.15,-11.431 8.15,-12.204 8.3,-12.354 8.3,-13.304
  region net GND_D: 5.3,-7.704 5.3,-8.671 5.225,-8.746 5.225,-9.544 5.3,-9.619 6,-9.619 6.05,-9.569 6.05,-8.796 5.9,-8.646 5.9,-7.696
  region net +5V_OUT: 7.3,-7.608 7.3,-8.575 7.225,-8.65 7.225,-9.448 7.3,-9.523 8,-9.523 8.05,-9.473 8.05,-8.7 7.9,-8.55 7.9,-7.6
  region net MAGNETICS_CT: -3.625,6 -3.485,5.86 -2.8,5.86 -2.8,5.35 -4.025,5.35 -4.1,5.425 -4.1,5.875 -3.975,6
Mid-Layer 1:
  rectangle net STO1_IN: 12.5,6.129 13.65,7.35
  rectangle net NetR17_2: 14.5,4.425 16.225,5.5
  rectangle net NetR18_2: 14.655,6.51 16.3,7.775
  rectangle net GND_D: 8.325,-2.525 9.65,-1.125
  region net PE: 16.735,12.3 18.695,10.341 19.555,10.341 19.555,7.295 19,6.74 cw(c19,8.506) 17.751,7.257 16.42,8.589 ccw(c15.4,7.569) 15.4,9.011 15.25,9.011 15.25,12.3
  region net PH_A: 20.15,-4.425 20.425,-4.425 21,-5 21,-8.41 20.483,-8.927 cw(c19.864,-8.536) 20.025,-9.25 18.647,-9.25 cw(c18.647,-8.127) 17.852,-8.921 17.447,-8.515 ccw(c15.651,-10.311) 15.651,-7.771 13.391,-7.771 cw(c13.391,-7.155) 12.956,-7.591 cw(c13.775,-6.975) 12.75,-6.975 12.75,-5.25 cw(c13.575,-5.25) 13.575,-4.425
  region net PH_C: 20.447,5.547 20.717,5.383 20.89,5.26 21,5.15 21,1.76 20.42,1.18 20.04,1.175 16.697,1.175 ccw(c16.697,0.72) 16.375,1.042 15.844,0.511 cw(c15.275,1.079) 15.275,0.275 13.517,0.275 cw(c13.517,1.042) 12.75,1.042 12.75,3.025 cw(c13.55,3.025) 13.55,3.825 16.15,3.825 ccw(c16.15,4.368) 16.534,3.984 16.937,4.387 17.859,5.309 cw(c18.666,4.525) 18.65,5.65 20.2,5.65 cw(c20.2,5.3)
  region net PH_B: 20.5,0.6 21,0.1 21,-3.3 20.425,-3.875 20.035,-3.875 16.402,-3.875 16.4,-3.874 13.549,-3.874 cw(c13.549,-3.075) 12.75,-3.075 12.75,-1 cw(c13.45,-1) 13.45,-0.3 15.775,-0.3 ccw(c15.775,0.131) 16.08,-0.174 16.7,0.446 cw(c17.071,0.075) 17.071,0.6
  region net +5V_OUT: 7.06,-1.12 7.205,-0.975 7.95,-0.975 8.075,-1.1 8.075,-1.575 7.85,-1.8 7.875,-1.825 7.875,-2.425 7.75,-2.55 7.55,-2.55 7.475,-2.475 7.475,-2.1 6.823,-1.448 6.823,-1.177 7.025,-0.975
  pour cut-out: -2.125,7.72 -6.355,7.72 -7.775,6.3 -7.575,6.1 -7.575,2.655 -7.345,2.425 -6.675,2.425 -6.32,2.78 -6.32,4.765 -5.705,5.38 -4.77,5.38 -3.4,6.75 -2.31,6.75
  pour cut-out: 0.125,11.35 0.125,11.307 2.657,8.775 2.657,6.839 1.835,6.017 0.383,6.017 -0.004,6.404 -0.004,11.246 0.1,11.35
  pour cut-out: 6.865,7.912 6.237,8.54 3.35,8.54 3.35,3.585 3.785,3.15 5.237,3.15 6.306,4.219 6.125,4.4 6.125,7.18 6.875,7.93
  region net BRAKE_OUT: -6.178,0.147 -6.008,-0.022 -6.008,-0.075 -6.179,-0.246 -6.179,-0.525 -6.375,-0.525 -6.637,-0.787 -6.637,-0.856 -6.84,-1.06 -7.225,-1.06 -7.275,-1.01 -7.275,0 -7.128,0.147
  pour cut-out: -6.636,-11.675 -8.575,-13.614 -8.575,-14.426 -8.5,-14.501 -8.498,-14.498 -3.3,-14.498 -3.3,-11.865 -3.49,-11.675
  region net STO2_IN: 12.868,5.84 12.7,5.672 12.7,4.618 12.763,4.55 13.875,4.55 14.1,4.775 14.1,5.55 13.81,5.84
  pour cut-out: -6.3,9.525 -6.3,10.675 -5.4,10.675 -5.125,10.95 -5.125,11.675 -5.625,12.175 -8.65,12.175 -9.4,11.425 -9.387,9.188 -9.4,9.175 -9.4,7.775 -7.85,6.225 -6.15,6.225 -4.375,8 -4.375,9.35 -4.525,9.5 -4.65,9.525
  pour cut-out: 6.662,10.312 6.25,10.725 5.675,10.725 5.525,10.875 5.525,11.925 5.75,12.15 6.875,12.15 7.575,12.85 9.4,12.85 9.6,12.65 9.6,9.225 9.275,8.925 8.15,7.8 5.375,7.8 5.275,7.9 5.275,9.5 6.175,9.5 6.65,9.975 6.65,10.3
Mid-Layer 2:
  region net PE: 16.735,12.3 18.695,10.341 19.555,10.341 19.555,7.295 19,6.74 cw(c19,8.506) 17.751,7.257 16.42,8.589 ccw(c15.4,7.569) 15.4,9.011 15.25,9.011 15.25,12.3
  region net +LOGIC_DCDC: -11.725,-13.563 cw(c-11.362,-13.563) -11.362,-13.2 -9.125,-13.2 cw(c-9.125,-13.45) -8.875,-13.45 -8.875,-13.8 cw(c-9.225,-13.8) -9.225,-14.15 -11.55,-14.15 cw(c-11.55,-13.975) -11.725,-13.975
  region net PH_B: 20.5,0.6 21,0.1 21,-3.3 20.425,-3.875 20.035,-3.875 16.402,-3.875 16.4,-3.874 13.549,-3.874 cw(c13.549,-3.075) 12.75,-3.075 12.75,-1 cw(c13.45,-1) 13.45,-0.3 15.775,-0.3 ccw(c15.775,0.131) 16.08,-0.174 16.7,0.446 cw(c17.071,0.075) 17.071,0.6
  region net PH_C: 20.447,5.547 20.717,5.383 20.89,5.26 21,5.15 21,1.76 20.42,1.18 20.04,1.175 16.697,1.175 ccw(c16.697,0.72) 16.375,1.042 15.844,0.511 cw(c15.275,1.079) 15.275,0.275 13.517,0.275 cw(c13.517,1.042) 12.75,1.042 12.75,3.025 cw(c13.55,3.025) 13.55,3.825 16.15,3.825 ccw(c16.15,4.368) 16.534,3.984 16.937,4.387 17.859,5.309 cw(c18.666,4.525) 18.65,5.65 20.2,5.65 cw(c20.2,5.3)
  region net PH_A: 20.15,-4.425 20.425,-4.425 21,-5 21,-8.41 20.483,-8.927 cw(c19.864,-8.536) 20.025,-9.25 18.647,-9.25 cw(c18.647,-8.127) 17.852,-8.921 17.447,-8.515 ccw(c15.651,-10.311) 15.651,-7.771 13.391,-7.771 cw(c13.391,-7.155) 12.956,-7.591 cw(c13.775,-6.975) 12.75,-6.975 12.75,-5.25 cw(c13.575,-5.25) 13.575,-4.425
  region net GND_P: -20.433,3.708 -20.716,3.425 -20.875,3.425 -21,3.3 -21,-0.075 -20.75,-0.325 -17.925,-0.325 -17.8,-0.3 -17.35,-0.125 -16.075,0.4 -13.725,0.4 ccw(c-13.725,1.374) -12.751,1.374 -12.751,1.741 ccw(c-13.935,1.8) -12.75,1.8 -12.75,2.7 -12.75,3.275 ccw(c-13.4,3.275) -13.4,3.925 -19.875,3.925 ccw(c-19.875,3.1)
  region net +V_BUS: -18.375,9.975 cw(c-18.375,8.618) -17.415,9.577 -16.638,8.8 ccw(c-15.738,9.7) -15.738,8.427 -13.227,8.427 cw(c-13.227,7.95) -12.75,7.95 -12.75,7.675 -12.75,5.25 cw(c-13.5,5.25) -13.5,4.5 -19.897,4.5 cw(c-19.896,5.057) -19.9,4.5 -20.5,4.5 -21,5 -21,8.409 -20.53,8.879 -19.533,9.889 cw(c-19.325,9.681) -19.325,9.975
  pour cut-out: -6.528,-10.959 -7.404,-10.959 -8.307,-10.056 -8.297,-9.19 -9.887,-7.6 -13.243,-7.598 -13.725,-8.08 -13.725,-9.181 -12.625,-10.279 -12.625,-11.216 -12.079,-11.762 -9.644,-11.762 -8.475,-12.931 -8.475,-14.5 -8.45,-14.475 -3.8,-14.475 -3.375,-14.05 -3.425,-14 -3.425,-10.25 -3.825,-9.85 -5.273,-9.85 -6.455,-11.032
  pour cut-out: -7.575,2.655 -7.345,2.425 -6.675,2.425 -6.32,2.78 -6.32,4.549 -5.489,5.38 -5.07,5.38 -4.01,6.44 -2.62,6.44 -1.92,7.14 -1.92,11.84 -2.31,12.23 -2.61,12.53 -2.61,14.48 -2.615,14.475 -5.575,14.475 -5.575,12.505 -5.94,12.14 -7.06,12.14 -7.325,11.875 -8.825,11.875 -9.38,11.32 -9.38,7.733 -7.575,5.928
  pour cut-out: 0.2,6.2 0.825,6.2 1.475,6.85 1.475,7.175 2.246,7.946 3.429,7.946 3.604,7.771 3.604,3.685 4,3.288 5.013,3.288 5.64,3.915 6.125,4.4 6.125,6.975 6.75,7.6 8.15,7.6 9.575,9.025 9.575,14.325 2.6,14.325 2.6,12.061 2.314,11.775 1.6,11.775 1.404,11.971 0.221,11.971 -0.004,11.746 -0.004,6.404
Mid-Layer 3:
  region net +V_BUS: -18.375,9.975 cw(c-18.375,8.618) -17.415,9.577 -16.638,8.8 ccw(c-15.738,9.7) -15.738,8.427 -13.227,8.427 cw(c-13.227,7.95) -12.75,7.95 -12.75,7.675 -12.75,5.25 cw(c-13.5,5.25) -13.5,4.5 -19.897,4.5 cw(c-19.896,5.057) -19.9,4.5 -20.5,4.5 -21,5 -21,8.409 -20.53,8.879 -19.533,9.889 cw(c-19.325,9.681) -19.325,9.975
  region net PE: 16.735,12.3 18.695,10.341 19.555,10.341 19.555,7.295 19,6.74 cw(c19,8.506) 17.751,7.257 16.42,8.589 ccw(c15.4,7.569) 15.4,9.011 15.25,9.011 15.25,12.3
  region net PH_B: 20.5,0.6 21,0.1 21,-3.3 20.425,-3.875 20.035,-3.875 16.402,-3.875 16.4,-3.874 13.549,-3.874 cw(c13.549,-3.075) 12.75,-3.075 12.75,-1 cw(c13.45,-1) 13.45,-0.3 15.775,-0.3 ccw(c15.775,0.131) 16.08,-0.174 16.7,0.446 cw(c17.071,0.075) 17.071,0.6
  region net PH_C: 20.447,5.547 20.717,5.383 20.89,5.26 21,5.15 21,1.76 20.42,1.18 20.04,1.175 16.697,1.175 ccw(c16.697,0.72) 16.375,1.042 15.844,0.511 cw(c15.275,1.079) 15.275,0.275 13.517,0.275 cw(c13.517,1.042) 12.75,1.042 12.75,3.025 cw(c13.55,3.025) 13.55,3.825 16.15,3.825 ccw(c16.15,4.368) 16.534,3.984 16.937,4.387 17.859,5.309 cw(c18.666,4.525) 18.65,5.65 20.2,5.65 cw(c20.2,5.3)
  region net PH_A: 20.15,-4.425 20.425,-4.425 21,-5 21,-8.41 20.483,-8.927 cw(c19.864,-8.536) 20.025,-9.25 18.647,-9.25 cw(c18.647,-8.127) 17.852,-8.921 17.447,-8.515 ccw(c15.651,-10.311) 15.651,-7.771 13.391,-7.771 cw(c13.391,-7.155) 12.956,-7.591 cw(c13.775,-6.975) 12.75,-6.975 12.75,-5.25 cw(c13.575,-5.25) 13.575,-4.425
  region net GND_P: -20.433,3.708 -20.716,3.425 -20.875,3.425 -21,3.3 -21,-0.075 -20.75,-0.325 -17.925,-0.325 -17.8,-0.3 -17.35,-0.125 -16.075,0.4 -13.725,0.4 ccw(c-13.725,1.374) -12.751,1.374 -12.751,1.741 ccw(c-13.935,1.8) -12.75,1.8 -12.75,2.7 -12.75,3.275 ccw(c-13.4,3.275) -13.4,3.925 -19.875,3.925 ccw(c-19.875,3.1)
Mid-Layer 4:
  region net +V_BUS: -18.375,9.975 cw(c-18.375,8.618) -17.415,9.577 -16.638,8.8 ccw(c-15.738,9.7) -15.738,8.427 -13.227,8.427 cw(c-13.227,7.95) -12.75,7.95 -12.75,7.675 -12.75,5.25 cw(c-13.5,5.25) -13.5,4.5 -19.897,4.5 cw(c-19.896,5.057) -19.9,4.5 -20.5,4.5 -21,5 -21,8.409 -20.53,8.879 -19.533,9.889 cw(c-19.325,9.681) -19.325,9.975
  region net PE: 16.735,12.3 18.695,10.341 19.555,10.341 19.555,7.295 19,6.74 cw(c19,8.506) 17.751,7.257 16.42,8.589 ccw(c15.4,7.569) 15.4,9.011 15.25,9.011 15.25,12.3
  region net PH_B: 20.5,0.6 21,0.1 21,-3.3 20.425,-3.875 20.035,-3.875 16.402,-3.875 16.4,-3.874 13.549,-3.874 cw(c13.549,-3.075) 12.75,-3.075 12.75,-1 cw(c13.45,-1) 13.45,-0.3 15.775,-0.3 ccw(c15.775,0.131) 16.08,-0.174 16.7,0.446 cw(c17.071,0.075) 17.071,0.6
  region net PH_C: 20.447,5.547 20.717,5.383 20.89,5.26 21,5.15 21,1.76 20.42,1.18 20.04,1.175 16.697,1.175 ccw(c16.697,0.72) 16.375,1.042 15.844,0.511 cw(c15.275,1.079) 15.275,0.275 13.517,0.275 cw(c13.517,1.042) 12.75,1.042 12.75,3.025 cw(c13.55,3.025) 13.55,3.825 16.15,3.825 ccw(c16.15,4.368) 16.534,3.984 16.937,4.387 17.859,5.309 cw(c18.666,4.525) 18.65,5.65 20.2,5.65 cw(c20.2,5.3)
  region net PH_A: 20.15,-4.425 20.425,-4.425 21,-5 21,-8.41 20.483,-8.927 cw(c19.864,-8.536) 20.025,-9.25 18.647,-9.25 cw(c18.647,-8.127) 17.852,-8.921 17.447,-8.515 ccw(c15.651,-10.311) 15.651,-7.771 13.391,-7.771 cw(c13.391,-7.155) 12.956,-7.591 cw(c13.775,-6.975) 12.75,-6.975 12.75,-5.25 cw(c13.575,-5.25) 13.575,-4.425
  region net GND_P: -20.433,3.708 -20.716,3.425 -20.875,3.425 -21,3.3 -21,-0.075 -20.75,-0.325 -17.925,-0.325 -17.8,-0.3 -17.35,-0.125 -16.075,0.4 -13.725,0.4 ccw(c-13.725,1.374) -12.751,1.374 -12.751,1.741 ccw(c-13.935,1.8) -12.75,1.8 -12.75,2.7 -12.75,3.275 ccw(c-13.4,3.275) -13.4,3.925 -19.875,3.925 ccw(c-19.875,3.1)
Mid-Layer 5:
  region net +V_BUS: -18.375,9.975 cw(c-18.375,8.618) -17.415,9.577 -16.638,8.8 ccw(c-15.738,9.7) -15.738,8.427 -13.227,8.427 cw(c-13.227,7.95) -12.75,7.95 -12.75,7.675 -12.75,5.25 cw(c-13.5,5.25) -13.5,4.5 -19.897,4.5 cw(c-19.896,5.057) -19.9,4.5 -20.5,4.5 -21,5 -21,8.409 -20.53,8.879 -19.533,9.889 cw(c-19.325,9.681) -19.325,9.975
  region net PE: 16.735,12.3 18.695,10.341 19.555,10.341 19.555,7.295 19,6.74 cw(c19,8.506) 17.751,7.257 16.42,8.589 ccw(c15.4,7.569) 15.4,9.011 15.25,9.011 15.25,12.3
  region net PH_B: 20.5,0.6 21,0.1 21,-3.3 20.425,-3.875 20.035,-3.875 16.402,-3.875 16.4,-3.874 13.549,-3.874 cw(c13.549,-3.075) 12.75,-3.075 12.75,-1 cw(c13.45,-1) 13.45,-0.3 15.775,-0.3 ccw(c15.775,0.131) 16.08,-0.174 16.7,0.446 cw(c17.071,0.075) 17.071,0.6
  region net PH_C: 20.447,5.547 20.717,5.383 20.89,5.26 21,5.15 21,1.76 20.42,1.18 20.04,1.175 16.697,1.175 ccw(c16.697,0.72) 16.375,1.042 15.844,0.511 cw(c15.275,1.079) 15.275,0.275 13.517,0.275 cw(c13.517,1.042) 12.75,1.042 12.75,3.025 cw(c13.55,3.025) 13.55,3.825 16.15,3.825 ccw(c16.15,4.368) 16.534,3.984 16.937,4.387 17.859,5.309 cw(c18.666,4.525) 18.65,5.65 20.2,5.65 cw(c20.2,5.3)
  region net PH_A: 20.15,-4.425 20.425,-4.425 21,-5 21,-8.41 20.483,-8.927 cw(c19.864,-8.536) 20.025,-9.25 18.647,-9.25 cw(c18.647,-8.127) 17.852,-8.921 17.447,-8.515 ccw(c15.651,-10.311) 15.651,-7.771 13.391,-7.771 cw(c13.391,-7.155) 12.956,-7.591 cw(c13.775,-6.975) 12.75,-6.975 12.75,-5.25 cw(c13.575,-5.25) 13.575,-4.425
  region net GND_P: -20.433,3.708 -20.716,3.425 -20.875,3.425 -21,3.3 -21,-0.075 -20.75,-0.325 -17.925,-0.325 -17.8,-0.3 -17.35,-0.125 -16.075,0.4 -13.725,0.4 ccw(c-13.725,1.374) -12.751,1.374 -12.751,1.741 ccw(c-13.935,1.8) -12.75,1.8 -12.75,2.7 -12.75,3.275 ccw(c-13.4,3.275) -13.4,3.925 -19.875,3.925 ccw(c-19.875,3.1)
  pour cut-out: -12.176,-5.9 -12.152,-5.924 -11.251,-5.924 -10.275,-6.9 -10.275,-10.341 -10.773,-10.84 -11.695,-10.84 -12.361,-10.173 -13.073,-8.456 -13.073,-6.564 -12.409,-5.9
Mid-Layer 6:
  rectangle net 3.3V_D: -6.375,-14.2 -5.33,-13.225
  rectangle net 5V_D: -7.53,-14.225 -6.605,-13.25
  region net +V_BUS: -18.375,9.975 cw(c-18.375,8.618) -17.415,9.577 -16.638,8.8 ccw(c-15.738,9.7) -15.738,8.427 -13.227,8.427 cw(c-13.227,7.95) -12.75,7.95 -12.75,7.675 -12.75,5.25 cw(c-13.5,5.25) -13.5,4.5 -19.897,4.5 cw(c-19.896,5.057) -19.9,4.5 -20.5,4.5 -21,5 -21,8.409 -20.53,8.879 -19.533,9.889 cw(c-19.325,9.681) -19.325,9.975
  region net PE: 16.735,12.3 18.695,10.341 19.555,10.341 19.555,7.295 19,6.74 cw(c19,8.506) 17.751,7.257 16.42,8.589 ccw(c15.4,7.569) 15.4,9.011 15.25,9.011 15.25,12.3
  region net PH_B: 20.5,0.6 21,0.1 21,-3.3 20.425,-3.875 20.035,-3.875 16.402,-3.875 16.4,-3.874 13.549,-3.874 cw(c13.549,-3.075) 12.75,-3.075 12.75,-1 cw(c13.45,-1) 13.45,-0.3 15.775,-0.3 ccw(c15.775,0.131) 16.08,-0.174 16.7,0.446 cw(c17.071,0.075) 17.071,0.6
  region net PH_C: 20.447,5.547 20.717,5.383 20.89,5.26 21,5.15 21,1.76 20.42,1.18 20.04,1.175 16.697,1.175 ccw(c16.697,0.72) 16.375,1.042 15.844,0.511 cw(c15.275,1.079) 15.275,0.275 13.517,0.275 cw(c13.517,1.042) 12.75,1.042 12.75,3.025 cw(c13.55,3.025) 13.55,3.825 16.15,3.825 ccw(c16.15,4.368) 16.534,3.984 16.937,4.387 17.859,5.309 cw(c18.666,4.525) 18.65,5.65 20.2,5.65 cw(c20.2,5.3)
  region net PH_A: 20.15,-4.425 20.425,-4.425 21,-5 21,-8.41 20.483,-8.927 cw(c19.864,-8.536) 20.025,-9.25 18.647,-9.25 cw(c18.647,-8.127) 17.852,-8.921 17.447,-8.515 ccw(c15.651,-10.311) 15.651,-7.771 13.391,-7.771 cw(c13.391,-7.155) 12.956,-7.591 cw(c13.775,-6.975) 12.75,-6.975 12.75,-5.25 cw(c13.575,-5.25) 13.575,-4.425
  region net GND_P: -20.433,3.708 -20.716,3.425 -20.875,3.425 -21,3.3 -21,-0.075 -20.75,-0.325 -17.925,-0.325 -17.8,-0.3 -17.35,-0.125 -16.075,0.4 -13.725,0.4 ccw(c-13.725,1.374) -12.751,1.374 -12.751,1.741 ccw(c-13.935,1.8) -12.75,1.8 -12.75,2.7 -12.75,3.275 ccw(c-13.4,3.275) -13.4,3.925 -19.875,3.925 ccw(c-19.875,3.1)
  region net 5V_D: -6.285,-0.744 -6.074,-0.533 -5.532,-0.533 -5.255,-0.809 -5.255,-1.205 -5.255,-2.058 -5.834,-2.637 -5.888,-2.637 -6.1,-2.425 -6.1,-1.5 -6.202,-1.398 cw(c-5.822,-1.018)
  pour cut-out: -12.176,-5.9 -12.152,-5.924 -11.251,-5.924 -10.275,-6.9 -10.275,-10.341 -10.773,-10.84 -11.768,-10.84 -12.457,-10.151 -13.073,-8.665 -13.073,-6.564 -12.409,-5.9
  region net +LOGIC_DCDC: -8.496,-1.871 -9.296,-1.871 -9.671,-2.246 -9.671,-3.446 -8.756,-4.362 -8.621,-4.362 -8.371,-4.112 -8.371,-1.996
Bottom Layer:
  rectangle net GND_D: 2.1,-9.125 2.7,-7.625
  rectangle net STO_RET: 14.48,5.075 15.35,5.975
  rectangle net PE1: -13.275,9.35 -11.875,11.066
  rectangle net GND_D: 6.61,9.375 10.91,11.025
  rectangle net 5V_D: -8.75,7.6 -8.25,12.8
  rectangle net GND_D: 9.9,-13.75 10.9,-12.875
  region net +LOGIC_PROTECTED: -7.28,5.68 cw(c-7.28,5.55) -7.15,5.55 -7.15,3.744 ccw(c-6.95,3.744) -7.055,3.574 cw(c-7.171,3.385) -6.95,3.385 -6.95,2.07 cw(c-7.15,2.07) -7.15,1.87 -8.016,1.87 cw(c-8.016,2.399) -8.39,2.025 ccw(c-8.538,1.877) -8.539,2.086 -9.639,2.086 ccw(c-9.639,1.925) -9.8,1.925 cw(c-9.9,1.925) -9.9,1.825 -10.225,1.825 -10.225,3.325 -8.953,3.325 ccw(c-8.953,3.931) -8.525,3.502 -8.276,3.752 ccw(c-8.651,4.127) -8.12,4.127 -8.12,5.585 cw(c-8.025,5.585) -8.025,5.68
  region net NetD21_1: -10.925,3.825 -9.184,3.825 ccw(c-9.184,4.375) -8.634,4.375 -8.634,5.616 cw(c-7.975,5.616) -7.975,6.275 -7.275,6.275 ccw(c-7.275,6.325) -7.225,6.325 -7.225,7.025 ccw(c-7.275,7.025) -7.275,7.075 -8.925,7.075 -10.725,7.075 -10.925,6.875
  region net +LOGIC_DCDC: -8.45,-9.847 cw(c-7.182,-9.847) -8.079,-8.95 -8.079,-8.317 ccw(c-8.4,-8.317) -8.4,-7.996 -9.296,-7.996 ccw(c-9.296,-8.225) -9.525,-8.225 -9.525,-10.754 ccw(c-9.275,-10.754) -9.275,-11.005 -8.68,-11.005 ccw(c-8.68,-10.775) -8.45,-10.775
  region net 5V_DCDC: -5.475,-5.6 -5.475,-6.925 -5.575,-7.025 -6.35,-7.025 -6.4,-6.975 cw(c-6.219,-6.794) -6.475,-6.794 -6.475,-5.925 -6.05,-5.5 -5.575,-5.5
  region net +LOGIC_DCDC: -8.481,1.319 -8.481,-1.279 -8.3,-1.471 -8.3,-4.4 -9.158,-4.4 cw(c-9.158,-4.258) -9.3,-4.258 -9.3,-3.368 ccw(c-9.523,-3.367) -9.365,-3.21 cw(c-9.04,-2.885) -9.5,-2.885 -9.5,0.5 -9.5,1.4 -9.4,1.5 -8.661,1.5
  region net GND_DCDC: -7.814,-5.489 -7.804,-5.5 -7.3,-5.5 -6.8,-6 -6.8,-6.405 ccw(c-6.524,-6.405) -6.795,-6.459 -6.795,-6.934 ccw(c-6.304,-6.934) -6.651,-7.281 cw(c-6.846,-7.469) -6.575,-7.474 -6.575,-7.737 -6.575,-9.7 -7.85,-9.7 -7.85,-9.213 -7.76,-9.094 ccw(c-8.494,-8.54) -7.575,-8.54 -7.575,-7.996 ccw(c-8.201,-7.996) -8.201,-7.37 -9.334,-7.37 -9.334,-7.293 ccw(c-10.065,-7.517) -9.525,-6.975 -9.8,-6.7 -9.8,-5.944 ccw(c-10.146,-5.943) -9.902,-5.698 -9.979,-5.621 cw(c-9.686,-5.328) -10.1,-5.328 -10.1,-5.1 -9.419,-5.1 -8.204,-5.1
  region net PE: 17.708,11.775 19.35,10.169 18.175,9.85 17.61,7.75 17.75,7.375 17.75,7.25 16.953,8.1 ccw(c16.41,7.557) 16.41,8.325 15.75,8.325 17.45,9.9
  region net PH_A: 20.55,-4.9 15.018,-4.9 cw(c15.018,-4.582) 14.887,-4.872 ccw(c14.449,-5.261) 14.449,-4.675 14.074,-4.675 ccw(c14.074,-5.999) 12.75,-6 ccw(c14.025,-6) 14.025,-7.275 16.495,-7.275 cw(c16.495,-8.555) 17.4,-7.65 17.509,-7.759 ccw(c19.341,-5.927) 19.341,-8.517 20.596,-8.517 ccw(c19.87,-8.535) 20.578,-8.375 20.55,-5.925
  region net PH_B: 18.875,0.186 18.117,0.186 ccw(c18.117,-1.909) 16.636,-0.428 cw(c16.038,0.17) 16.038,-0.675 14.05,-0.675 ccw(c14.05,-1.975) 12.75,-1.975 ccw(c14.205,-1.975) 14.205,-3.43 20.509,-3.43 ccw(c20.042,-3.4) 20.51,-3.4 ccw(c20.51,-3.285) 20.625,-3.285 20.625,0.025 ccw(c20.051,0.025) 20.602,0.186
  region net PH_C: 12.75,1.85 ccw(c13.9,1.85) 13.9,0.7 14.962,0.7 ccw(c14.962,2.663) 16.35,1.275 cw(c17.316,0.309) 17.316,1.675 17.904,1.675 20.55,1.675 20.55,5.3 19.261,5.3 ccw(c19.261,2.951) 17.6,4.612 17.035,4.047 cw(c15.203,5.879) 15.203,3.288 14.005,3.288 ccw(c14.005,2.034) 12.75,2.034
  region net GND_P: -20.65,3.366 cw(c-20.507,3.223) -20.507,3.425 -13.428,3.425 cw(c-13.428,2.748) -12.751,2.748 cw(c-14.042,2.7) -12.75,2.7 -12.75,1.8 cw(c-13.95,1.8) -13.95,0.6 -15.666,0.6 ccw(c-15.666,-1.316) -16.48,0.418 -17.627,-0.12 cw(c-18.024,0.824) -18.024,-0.2 -20.6,-0.2 cw(c-20.359,0.041) -20.7,0.041 -20.7,3.1 cw(c-20.007,3.107)
  region net +V_BUS: -13.271,7.121 -13,6.85 cw(c-13.64,6.21) -12.735,6.21 -12.525,6 -11.525,6 -11.435,5.91 -11.435,4.25 -11.685,4 -12.661,4 cw(c-12.661,4.699) -13.155,4.205 -13.85,4.9 -20.472,4.9 cw(c-20.472,4.972) -20.523,4.921 cw(c-20.017,5.38) -20.7,5.38 -20.7,5.776 -20.7,8.1 -20.7,8.136 cw(c-18.387,8.136) -20.689,8.363 cw(c-20.563,8.363) -20.563,8.489 -18.862,8.489 cw(c-18.862,6.26) -17.286,7.836 ccw(c-16.415,8.707) -16.415,7.475 -14.548,7.475 -14.125,7.475 cw(c-14.125,6.268)
  region net GND_DCDC: -9.867,-3.541 cw(c-10.156,-3.829) -9.748,-3.833 -9.751,-4.218 ccw(c-8.995,-4.224) -9.529,-4.759 -8.95,-5.338 -10.1,-5.338 -10.1,-4.266 -10.253,-3.897 cw(c-10.253,-3.565) -10.488,-3.8 cw(c-10.608,-3.511) -10.728,-3.8 -10.93,-3.717 ccw(c-11.22,-3.836) -11.1,-3.546 -11.1,-1.358 -11.44,-1.018 -12.042,-1.018 cw(c-12.042,0.529) -12.322,-0.993 ccw(c-12.553,-2.25) -13.043,-1.069 -13.088,-1.088 cw(c-13.357,-0.976) -13.246,-1.246 -13.5,-1.859 -13.5,-7 -13.6,-7.1 -16.4,-7.1 -16.5,-7 -16.5,-1.7 -16.3,-1.5 -15.3,-1.5 -14.9,-1.1 -14.015,-1.1 -13.083,-0.167 -12.679,0 -11.807,0 -11.176,0.261 cw(c-10.917,0.154) -11.024,0.413 -10.815,0.5 -10.525,0.5 cw(c-10.525,0.117) -10.142,0.117 -10.142,-0.983 -10,-1.125 -10,-3.281 ccw(c-9.693,-3.281) -9.91,-3.498
  region net GND_D: -6.725,9.625 -6.8,9.7 -6.8,10.1 -7.075,10.375 -7.475,10.375 -7.475,10.475 -7.75,10.85 -5.3,10.85 -4.925,10.475 -5.1,10.3 -6.05,10.3
  region net GND_A: -0.087,-2.9 -0.4,-2.9 -0.4,-2.35 -0.35,-2.35 0.043,-2.743
  region net GND_D: 4.25,11.325 4.125,11.2 4.125,10.625 4.35,10.4 5.71,10.4 6.635,9.475 6.975,9.475 6.975,10.875 7,10.9 4.65,10.9 4.375,11.175 4.375,11.325
  region net GND_A: -2.975,-9.412 -5.597,-9.412 -5.75,-9.26 -5.8,-9.31 -5.8,-11.325 -5.85,-11.375 -5.85,-11.35 -5.391,-10.891 -4.341,-10.891 -3.15,-9.7 -2.975,-9.7
  region net 5V_D: -8.9,8.95 -8.1,8.95 -8.1,11.65 -8.9,11.65
Multi-Layer:
  region net PE: 21,8.708 ccw(c19.208,8.708) 20.475,9.975 20.109,10.341 19,10.341 19,6.74 20.9,6.74 21,6.84

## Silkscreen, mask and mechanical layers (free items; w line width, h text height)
Top Solder:
  circle w0.1: c12.8,13.5 r0.7
  circle w0.1: c-12.8,13.5 r0.7
  lines w0.1: -13.3,13.388 -13.3,13.613 ; -13.1,13.2 -13.1,13.8 ; -12.9,13.05 -12.9,13.5 ; -12.9,13.95 -12.9,13.5 ; -12.3,13.5 -12.9,13.5 ; 12.325,13.5 12.9,13.5 ; 12.9,13.05 12.9,13.5 ; 12.9,13.95 12.9,13.5 ; 13.1,13.2 13.1,13.8 ; 13.3,13.388 13.3,13.613
  lines w0.15: -17.4,5.4 -16.6,5.4 ; -17,2.4 -17,3.2 ; -17,5 -17,5.8
  text "i044 / 01H6-1.2" at -12.62,12.6 h0.5 r270
  text "INGENIA" at -16.8,3.6 h0.9 r270
  text "C" at 17.35,1.5 h1.5 r90
  text "B" at 17.35,-2.75 h1.5 r90
  text "A" at 17.35,-7 h1.5 r90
